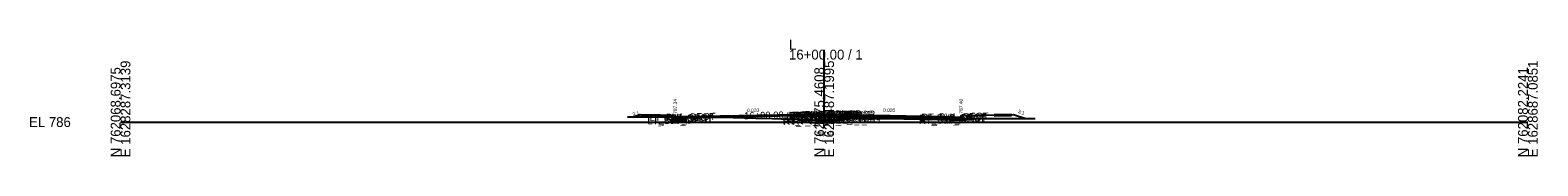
# Model space of a CAD drawing. Extents: x -26 to 4403, y -510 to 9556.
# Drawn here: x -25.7 to 402.8, y 5990.3 to 6023.4 of the extents above; entities that cross this region are included whole.
import ezdxf

# ---------------------------------------------------------------- set-up
doc = ezdxf.new("R2010")
doc.units = 0
for name, color, linetype in [('Default', 7, 'Continuous'), ('Exist CMT Pavement', 7, 'Continuous'), ('Exist Cross Section Cell', 7, 'Continuous'), ('Exist XS Center Line Elevation Label', 7, 'Continuous'), ('Exist XS Ground Line', 7, 'Continuous'), ('Exist XS Void Line', 7, 'Continuous'), ('Prop CMT Conc Surface', 7, 'Continuous'), ('Prop CMT Concrete Structures', 7, 'Continuous'), ('Prop CMT Pvmt Course 1', 7, 'Continuous'), ('Prop CMT Pvmt Course 1 CG', 7, 'Continuous'), ('Prop CMT Pvmt Course 1 Wedge', 7, 'Continuous'), ('Prop CMT Pvmt Course 2', 7, 'Continuous'), ('Prop CMT Pvmt Course 2 Wedge', 7, 'Continuous'), ('Prop CMT Pvmt Course 3', 7, 'Continuous'), ('Prop CMT Pvmt Course 3 Wedge', 7, 'Continuous'), ('Prop CMT Pvmt Surface', 7, 'Continuous'), ('Prop CMT Pvmt Wedge Surface 1', 7, 'Continuous'), ('Prop CMT Pvmt Wedge Surface 2', 7, 'Continuous'), ('Prop CMT Pvmt Wedge Surface 3', 7, 'Continuous'), ('Prop CMT Slope Grass', 7, 'Continuous'), ('Prop CMT Subgrade Earthwork', 7, 'Continuous'), ('Prop XS Hydro Elevations', 7, 'Continuous'), ('Prop XS SE Text', 7, 'Continuous'), ('Prop XS Side Slope Text', 7, 'Continuous'), ('Scratch_Level_0', 7, 'Continuous')]:
    doc.layers.add(name, color=color, linetype=linetype)

msp = doc.modelspace()

# ---------------------------------------------------------------- linework, layer by layer
at = {"layer": 'Exist CMT Pavement'}
msp.add_line((168.25, 6001.37), (160.65, 6001.37), dxfattribs=at)
msp.add_lwpolyline([(168.25, 6001.37), (170.87, 6001.43), (180.58, 6001.14), (185.26, 6001), (192.97, 6000.77), (200, 6000.59), (202.35, 6000.53), (203.52, 6000.51)], dxfattribs=at)
at = {"layer": 'Exist Cross Section Cell'}
for p, q in [((200, 6000), (200, 6020.58)), ((0, 6000), (200, 6000)), ((200, 6000), (400, 6000))]:
    msp.add_line(p, q, dxfattribs=at)
at = {"layer": 'Exist XS Ground Line'}
msp.add_lwpolyline([(168.25, 6001.37), (170.87, 6001.43), (180.58, 6001.14), (185.26, 6001), (192.97, 6000.77), (200, 6000.59), (202.35, 6000.53), (203.58, 6000.51), (204.07, 6000.54), (205.74, 6000.61), (206.09, 6000.86), (206.47, 6001), (206.58, 6001.02)], dxfattribs=at)
at = {"layer": 'Exist XS Void Line'}
for p, q in [((168.25, 6001.37), (144.11, 6001.37)), ((206.58, 6001.02), (259.94, 6001.02))]:
    msp.add_line(p, q, dxfattribs=at)
at = {"layer": 'Prop CMT Conc Surface'}
for points in [[(153.15, 6001.93), (148.15, 6002.03)], [(157.65, 6001.34), (157.65, 6001.84), (157.15, 6001.84)], [(159.65, 6001.46), (157.65, 6001.34)], [(236.9, 6001.52), (238.9, 6001.4)], [(238.9, 6001.4), (238.91, 6001.9), (239.41, 6001.9)], [(248.28, 6002.09), (253.28, 6002.19)]]:
    msp.add_lwpolyline(points, dxfattribs=at)
at = {"layer": 'Prop CMT Concrete Structures'}
for points in [[(148.15, 6001.69), (148.15, 6002.03)], [(148.15, 6002.03), (153.15, 6001.93)], [(153.15, 6001.59), (148.15, 6001.69)], [(153.15, 6001.93), (153.15, 6001.59)], [(159.65, 6001.46), (157.65, 6001.34), (157.65, 6001.84), (157.15, 6001.84)], [(157.15, 6001.84), (157.15, 6000.82), (159.65, 6000.87)], [(159.65, 6000.87), (159.65, 6001.46)], [(196, 6002.34), (195.99, 6002.51), (195.24, 6002.76), (194, 6002.78), (192.76, 6002.52), (192.01, 6002.27), (192, 6002.1)], [(192, 6002.1), (196, 6002.34)], [(236.9, 6001.52), (238.9, 6001.4), (238.91, 6001.9), (239.41, 6001.9)], [(239.41, 6001.9), (239.4, 6000.89), (236.9, 6000.94)], [(236.9, 6000.94), (236.9, 6001.52)], [(253.28, 6002.19), (248.28, 6002.09)], [(248.28, 6002.09), (248.28, 6001.76)], [(248.28, 6001.76), (253.28, 6001.86)], [(253.28, 6001.86), (253.28, 6002.19)]]:
    msp.add_lwpolyline(points, dxfattribs=at)
at = {"layer": 'Prop CMT Pvmt Course 1'}
for points in [[(192, 6002.1), (159.65, 6001.46)], [(159.65, 6001.21), (192, 6001.85)], [(159.65, 6001.46), (159.65, 6001.21)], [(159.65, 6001.46), (159.65, 6001.21)], [(159.65, 6001.46), (159.65, 6001.21), (159.65, 6001.21), (159.65, 6001.33)], [(192, 6002.1), (196, 6002.34)], [(192, 6001.85), (192, 6002.1)], [(192, 6001.85), (192, 6002.1)], [(196, 6002.09), (192, 6001.85)], [(192, 6001.98), (192, 6001.85), (192, 6001.85)], [(196, 6002.34), (196, 6002.09)], [(196, 6002.09), (196, 6002.34)], [(200, 6002.01), (200, 6002.26)], [(200, 6002.26), (236.9, 6001.52)], [(200, 6002.01), (200, 6002.26)], [(200, 6002.01), (200, 6002.14)], [(200, 6002.14), (200, 6002.14)], [(200, 6002.14), (200, 6002.01)], [(203.53, 6002.07), (200, 6002.14)], [(200, 6002.14), (200, 6002.01), (200, 6002.01)], [(200, 6002.01), (200, 6002.01)], [(203.53, 6001.94), (203.53, 6002.07)], [(236.9, 6001.27), (203.53, 6001.94)], [(236.9, 6001.52), (236.9, 6001.27)]]:
    msp.add_lwpolyline(points, dxfattribs=at)
msp.add_lwpolyline([(196, 6002.09), (196, 6002.22), (196, 6002.22), (196, 6002.09)], close=True, dxfattribs=at)
at = {"layer": 'Prop CMT Pvmt Course 1 CG'}
for points in [[(159.65, 6000.87), (156.65, 6000.81), (156.31, 6000.47)], [(156.31, 6000.47), (159.65, 6000.54)], [(236.9, 6000.94), (239.9, 6000.88), (240.24, 6000.54)], [(240.24, 6000.54), (236.9, 6000.61)]]:
    msp.add_lwpolyline(points, dxfattribs=at)
at = {"layer": 'Prop CMT Pvmt Course 1 Wedge'}
for points in [[(159.65, 6001.21), (159.65, 6001.33)], [(192, 6001.98), (192, 6001.85)], [(196, 6002.22), (202.35, 6002.09), (203.53, 6002.07)], [(200, 6002.01), (200, 6002.14)], [(203.53, 6001.94), (202.35, 6001.97), (200, 6002.01)], [(203.53, 6002.07), (203.53, 6001.94)]]:
    msp.add_lwpolyline(points, dxfattribs=at)
at = {"layer": 'Prop CMT Pvmt Course 2'}
for points in [[(192, 6001.85), (159.65, 6001.21)], [(159.65, 6001.21), (159.65, 6000.87)], [(159.65, 6001.21), (159.65, 6000.87)], [(159.65, 6000.87), (159.65, 6000.87), (159.65, 6001.21), (159.65, 6001.21)], [(159.65, 6001.21), (159.65, 6000.87)], [(159.65, 6000.87), (160.65, 6000.89)], [(192, 6001.85), (196, 6002.09)], [(192, 6001.52), (192, 6001.85)], [(196, 6001.76), (192, 6001.52)], [(196, 6002.09), (196, 6001.76)], [(196, 6001.76), (196, 6002.09)], [(200, 6001.68), (200, 6002.01)], [(203.53, 6001.61), (203.53, 6001.94)], [(203.53, 6001.94), (236.9, 6001.27)], [(236.9, 6000.94), (203.53, 6001.61)], [(236.9, 6001.27), (236.9, 6000.94)]]:
    msp.add_lwpolyline(points, dxfattribs=at)
at = {"layer": 'Prop CMT Pvmt Course 2 Wedge'}
for points in [[(159.65, 6000.87), (159.65, 6001.21)], [(192, 6001.85), (192, 6001.52)], [(196, 6002.09), (202.35, 6001.97), (203.53, 6001.94)], [(200, 6001.68), (200, 6002.01)], [(203.53, 6001.61), (202.35, 6001.63), (200, 6001.68)], [(203.53, 6001.94), (203.53, 6001.61)]]:
    msp.add_lwpolyline(points, dxfattribs=at)
at = {"layer": 'Prop CMT Pvmt Course 3'}
for points in [[(160.65, 6000.89), (159.65, 6000.87)], [(159.65, 6000.87), (159.65, 6000.54)], [(159.65, 6000.54), (160.65, 6000.56)], [(192, 6001.52), (196, 6001.76)], [(203.53, 6001.61), (236.9, 6000.94)], [(203.53, 6001.28), (203.53, 6001.61)], [(236.9, 6000.61), (203.53, 6001.28)], [(236.9, 6000.94), (236.9, 6000.61)]]:
    msp.add_lwpolyline(points, dxfattribs=at)
at = {"layer": 'Prop CMT Pvmt Course 3 Wedge'}
for points in [[(196, 6001.76), (202.35, 6001.63), (203.53, 6001.61)], [(203.53, 6000.51), (202.35, 6000.53), (200, 6000.59)], [(203.53, 6001.61), (203.53, 6000.51)]]:
    msp.add_lwpolyline(points, dxfattribs=at)
at = {"layer": 'Prop CMT Pvmt Surface'}
for points in [[(192, 6002.1), (159.65, 6001.46)], [(192, 6002.1), (196, 6002.34)], [(196, 6002.34), (236.9, 6001.52)]]:
    msp.add_lwpolyline(points, dxfattribs=at)
at = {"layer": 'Prop CMT Pvmt Wedge Surface 1'}
for points in [[(159.65, 6001.21), (159.65, 6001.46)], [(159.65, 6001.33), (159.65, 6001.21), (159.65, 6001.21)], [(192, 6002.1), (192, 6001.85), (192, 6001.85), (192, 6001.98)], [(200, 6002.14), (203.53, 6002.07)], [(203.53, 6002.07), (203.53, 6001.94)], [(203.53, 6001.94), (236.9, 6001.27)], [(236.9, 6001.27), (236.9, 6001.52)]]:
    msp.add_lwpolyline(points, dxfattribs=at)
at = {"layer": 'Prop CMT Pvmt Wedge Surface 2'}
for points in [[(159.65, 6001.21), (159.65, 6001.46)], [(192, 6002.1), (192, 6001.85)], [(200, 6002.01), (236.9, 6001.27)], [(236.9, 6001.27), (236.9, 6001.52)]]:
    msp.add_lwpolyline(points, dxfattribs=at)
at = {"layer": 'Prop CMT Pvmt Wedge Surface 3'}
for points in [[(159.65, 6000.87), (159.65, 6001.46)], [(192, 6002.1), (192, 6001.52)], [(200, 6001.68), (236.9, 6000.94)], [(236.9, 6000.94), (236.9, 6001.52)]]:
    msp.add_lwpolyline(points, dxfattribs=at)
at = {"layer": 'Prop CMT Slope Grass'}
for points in [[(157.15, 6001.84), (147.65, 6002.03), (145.66, 6001.37)], [(239.41, 6001.9), (253.78, 6002.19), (257.3, 6001.02)]]:
    msp.add_lwpolyline(points, dxfattribs=at)
at = {"layer": 'Prop CMT Subgrade Earthwork'}
msp.add_line((160.65, 6000.56), (160.65, 6001.37), dxfattribs=at)
for points in [[(159.65, 6000.54), (156.31, 6000.47), (154.9, 6001.88)], [(160.65, 6000.56), (159.65, 6000.54)], [(159.65, 6000.54), (159.65, 6000.54)], [(159.65, 6000.54), (159.66, 6000.53)], [(203.53, 6001.28), (203.52, 6000.51)], [(203.53, 6001.28), (236.9, 6000.61)], [(203.53, 6001.28), (203.53, 6000.51)], [(236.9, 6000.61), (240.24, 6000.54), (241.65, 6001.95)]]:
    msp.add_lwpolyline(points, dxfattribs=at)

# ---------------------------------------------------------------- texts
at = {"layer": 'Default'}
msp.add_text('-', height=0.0001, dxfattribs=at).set_placement((0, 6000))
at = {"layer": 'Exist Cross Section Cell'}
for s, p in [('L', (190, 6020.58)), ('16+00.00 / 1', (190, 6017.78)), ('EL 786', (-26, 5998.6))]:
    msp.add_text(s, height=2.8, dxfattribs=at).set_placement(p)
for s, p in [('E 1628287.3139', (2.8, 5990)), ('E 1628487.1995', (202.8, 5990)), ('E 1628687.0851', (402.8, 5990)), ('N 762068.6975', (0, 5990)), ('N 762075.4608', (200, 5990)), ('N 762082.2241', (400, 5990))]:
    msp.add_text(s, height=2.8, rotation=90, dxfattribs=at).set_placement(p)
at = {"layer": 'Exist XS Center Line Elevation Label'}
msp.add_text('786.59', height=1.2, dxfattribs=at).set_placement((197.48, 5995.99))
at = {"layer": 'Prop XS Hydro Elevations'}
for s, p in [('787.34', (158.15, 6002.34)), ('787.40', (239.4, 6002.4))]:
    msp.add_text(s, height=1, rotation=90, dxfattribs=at).set_placement(p)
at = {"layer": 'Prop XS SE Text'}
for rotation, p in [(1.1456, (178.05, 6002.82)), (358.8544, (216.72, 6002.93))]:
    msp.add_text('0.020', height=1, rotation=rotation, dxfattribs=at).set_placement(p)
at = {"layer": 'Prop XS Side Slope Text'}
for rotation, p in [(18.4349, (145.69, 6001.66)), (341.5651, (254.96, 6002.64))]:
    msp.add_text('3:1', height=1, rotation=rotation, dxfattribs=at).set_placement(p)
at = {"layer": 'Scratch_Level_0'}
for s, p in [('LT_Sub_OEOT', (149.75, 5999.34)), ('LT_PV2_OEOT', (149.84, 6000.01)), ('LT_PV3_OEOT', (149.84, 5999.68)), ('LT_PV1_OEOT', (150.41, 6000.27)), ('16+00.00', (177.27, 6000.81)), ('RT_PV_IEEOP_EG', (188.16, 5999.35)), ('RT_PV_Sub_Tie_Out', (188.44, 5999.21)), ('LT_Sub_OEEOP', (189.23, 6000.13)), ('LT_PV2_OEEOP', (189.33, 6000.8)), ('LT_PV3_OEEOP', (189.33, 6000.47)), ('LT_PV1_OEEOP', (189.9, 6000.94)), ('RT_PV2_IEEOP', (189.93, 6000.81)), ('RT_PV3_IEEOP', (189.93, 6000.48)), ('LT_PV2_IEEOP', (189.98, 6000.81)), ('RT_PV1_IEEOP', (190.49, 6000.95)), ('LT_PV1_IEEOP', (190.54, 6000.95)), ('RT_PV_OEEOP_EG', (191.05, 5999.26)), ('RT_Sub_OEEOP', (192.72, 6000.06)), ('RT_PV2_OEEOP', (192.81, 6000.73)), ('RT_PV3_OEEOP', (192.81, 6000.39)), ('RT_PV1_OEEOP', (193.38, 6000.86)), ('PV2_PGL', (193.93, 6000.89)), ('PV1_PGL', (194.49, 6001.15)), ('RT_Sub_OEOT', (226.96, 5999.41)), ('RT_PV2_OEOT', (227.05, 6000.08)), ('RT_PV3_OEOT', (227.05, 5999.74)), ('RT_PV1_OEOT', (227.62, 6000.34))]:
    msp.add_text(s, height=2, rotation=1.1458, dxfattribs=at).set_placement(p)

doc.saveas('drawing.dxf')
